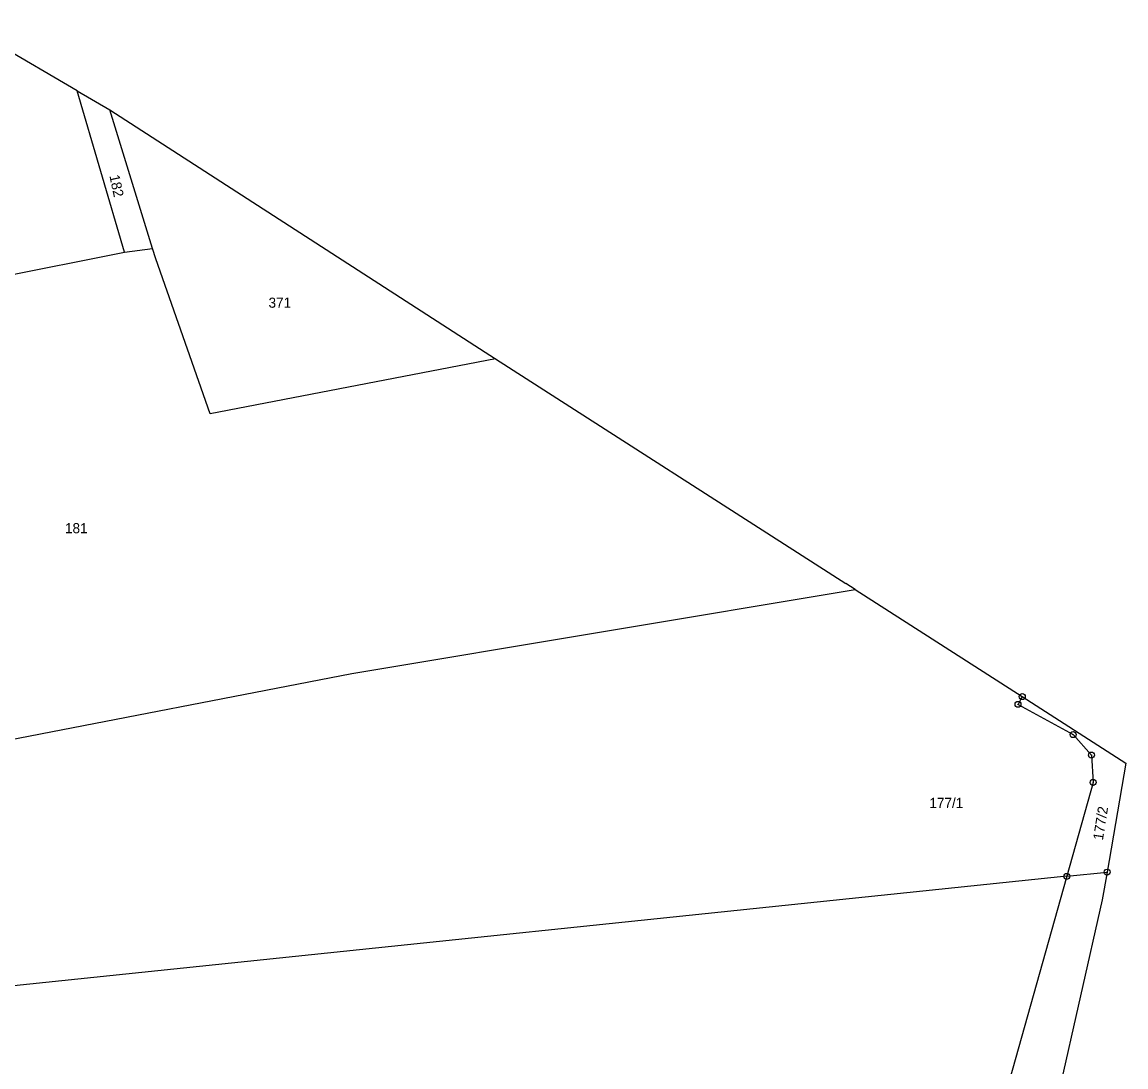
# Model space of a CAD drawing. Extents: x -645290 to -643454, y -1064771 to -1062356.
# Drawn here: x -643640.1 to -643454.5, y -1063081.6 to -1062906 of the extents above; entities that cross this region are included whole.
import ezdxf
from ezdxf.enums import TextEntityAlignment as Align

# ---------------------------------------------------------------- set-up
doc = ezdxf.new("R2010")
doc.units = 0
doc.header["$LTSCALE"] = 0.68
doc.layers.add('1', color=7, linetype='Continuous', lineweight=25)
doc.layers.add('8', color=7, linetype='Continuous', lineweight=25)
doc.layers.add('2', color=7, linetype='Continuous')

msp = doc.modelspace()

# ---------------------------------------------------------------- linework, layer by layer
at = {"layer": '1'}
for p, q in [((-643630.79, -1062917.54), (-643650.6, -1062905.99)), ((-643630.79, -1062917.54), (-643625.31, -1062920.74)), ((-643622.87, -1062944.69), (-643630.79, -1062917.54)), ((-643625.31, -1062920.74), (-643560.5, -1062962.61)), ((-643618.14, -1062944.06), (-643625.31, -1062920.74)), ((-643710.27, -1062962.15), (-643622.87, -1062944.69)), ((-643622.87, -1062944.69), (-643618.14, -1062944.06)), ((-643617.6, -1062945.82), (-643618.14, -1062944.06)), ((-643608.46, -1062971.87), (-643617.6, -1062945.82)), ((-643560.5, -1062962.61), (-643608.46, -1062971.87)), ((-643560.5, -1062962.61), (-643501.57, -1063000.38)), ((-643584.65, -1063015.51), (-643500.03, -1063001.37)), ((-643500.03, -1063001.37), (-643501.57, -1063000.38)), ((-643500.03, -1063001.37), (-643471.92, -1063019.39)), ((-643653.48, -1063028.85), (-643584.65, -1063015.51)), ((-643471.92, -1063019.39), (-643472.64, -1063020.69)), ((-643471.92, -1063019.39), (-643454.5, -1063030.55)), ((-643472.64, -1063020.69), (-643463.38, -1063025.78)), ((-643454.5, -1063030.55), (-643457.66, -1063048.89)), ((-643460.01, -1063033.81), (-643464.44, -1063049.6)), ((-643464.44, -1063049.6), (-643644.18, -1063068.28)), ((-643464.44, -1063049.6), (-643475.88, -1063090.34)), ((-643464.44, -1063049.6), (-643457.66, -1063048.89)), ((-643457.66, -1063048.89), (-643458.47, -1063053.57)), ((-643458.47, -1063053.57), (-643481.61, -1063155.97))]:
    msp.add_line(p, q, dxfattribs=at)
msp.add_lwpolyline([(-643463.38, -1063025.78), (-643460.3, -1063029.21), (-643460.01, -1063033.81)], dxfattribs=at)
at = {"layer": '8'}
for centre, radius in [((-643471.92, -1063019.3899), 0.5), ((-643471.92, -1063019.3899), 0.0303), ((-643472.64, -1063020.6899), 0.5), ((-643472.64, -1063020.6899), 0.0303), ((-643463.38, -1063025.7799), 0.5), ((-643463.38, -1063025.7799), 0.0303), ((-643460.3, -1063029.2099), 0.5), ((-643460.3, -1063029.2099), 0.0303), ((-643460.01, -1063033.8099), 0.5), ((-643460.01, -1063033.8099), 0.0303), ((-643464.44, -1063049.5999), 0.5), ((-643464.44, -1063049.5999), 0.0303), ((-643457.66, -1063048.8899), 0.5), ((-643457.66, -1063048.8899), 0.0303)]:
    msp.add_circle(centre, radius, dxfattribs=at)

# ---------------------------------------------------------------- texts
at = {"layer": '2'}
msp.add_text('182', height=1.7, rotation=282, dxfattribs=at).set_placement((-643625.395, -1062931.838))
for s, p in [('371', (-643596.739, -1062954.015)), ('177/1', (-643484.69, -1063038.104))]:
    msp.add_text(s, height=1.7, dxfattribs=at).set_placement(p, align=Align.CENTER)
msp.add_text('181', height=1.7, dxfattribs=at).set_placement((-643632.85, -1062991.925))
msp.add_text('177/2', height=1.7, rotation=81, dxfattribs=at).set_placement((-643457.9286, -1063040.808), align=Align.CENTER)

doc.saveas('drawing.dxf')
